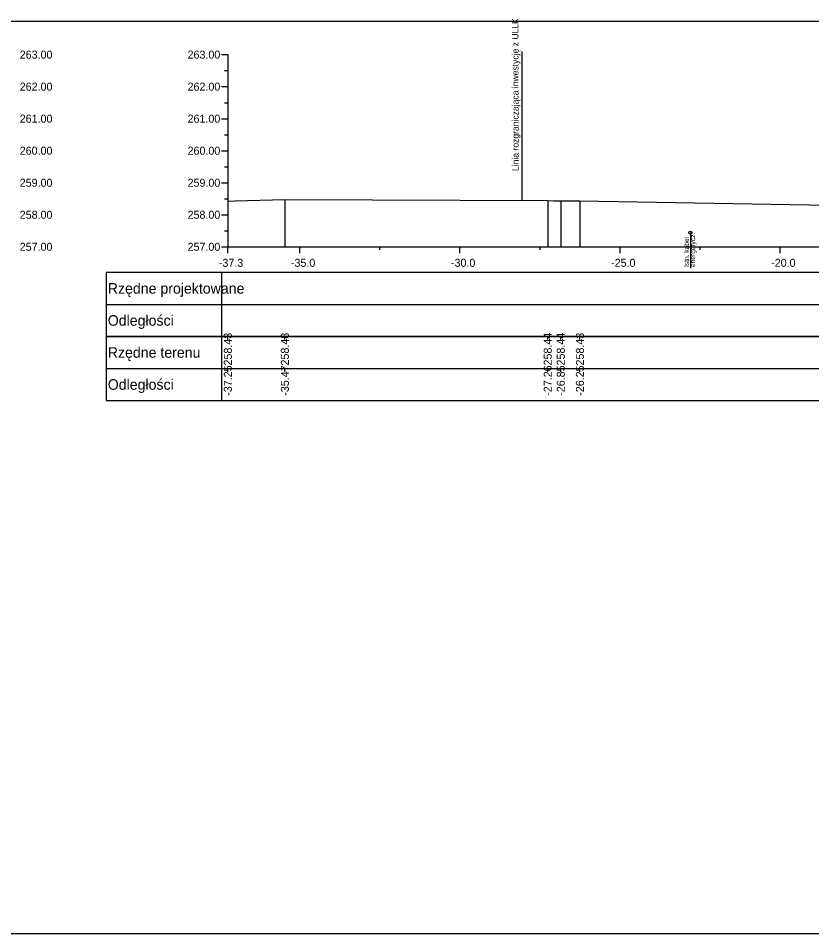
# Model space of a CAD drawing. Extents: x 6516023 to 6560129, y 5513077 to 5529206.
# Drawn here: x 6516993.92 to 6517018.7, y 5514451.16 to 5514479.74 of the extents above; entities that cross this region are included whole.
import ezdxf

# ---------------------------------------------------------------- set-up
doc = ezdxf.new("R2010")
doc.units = 0
for name, color, linetype in [('TOR_PRZEK_P-kable', 7, 'Continuous'), ('TOR_PRZEK_P-tabelka istniejace', 7, 'Continuous'), ('TOR_PRZEK_P-tabelka projektowane', 7, 'Continuous'), ('TOR_PRZEK_P-teren istniejacy', 7, 'Continuous'), ('TOR_PRZEK_P-uklad odniesienia', 7, 'Continuous'), ('TOR_PS_T-granica PKP-projektowana', 7, 'Continuous'), ('TOR_RAMKI-ramka+tabelka 1', 7, 'Continuous')]:
    doc.layers.add(name, color=color, linetype=linetype)

msp = doc.modelspace()

# ---------------------------------------------------------------- linework, layer by layer
at = {"layer": 'TOR_PRZEK_P-kable'}
msp.add_line((6517014.909, 5514473.047), (6517014.909, 5514471.937), dxfattribs=at)
msp.add_circle((6517014.909, 5514473.047), 0.05, dxfattribs=at)
at = {"layer": 'TOR_PRZEK_P-tabelka istniejace'}
for p, q in [((6516996.663, 5514469.806), (6516996.663, 5514467.806)), ((6517000.263, 5514469.806), (6517000.263, 5514467.806)), ((6517000.463, 5514469.706), (6517000.463, 5514469.806)), ((6517002.244, 5514469.706), (6517002.244, 5514469.806)), ((6517010.454, 5514469.706), (6517010.454, 5514469.806)), ((6517010.861, 5514469.706), (6517010.861, 5514469.806)), ((6517011.459, 5514469.706), (6517011.459, 5514469.806)), ((6516996.663, 5514468.806), (6517080.463, 5514468.806)), ((6517000.463, 5514468.706), (6517000.463, 5514468.806)), ((6517002.244, 5514468.706), (6517002.244, 5514468.806)), ((6517010.454, 5514468.706), (6517010.454, 5514468.806)), ((6517010.861, 5514468.706), (6517010.861, 5514468.806)), ((6517011.459, 5514468.706), (6517011.459, 5514468.806))]:
    msp.add_line(p, q, dxfattribs=at)
for points in [[(6517000.463, 5514474.035), (6517000.463, 5514472.806), (6517000.463, 5514472.676), (6517000.463, 5514472.606)], [(6517002.244, 5514474.084), (6517002.244, 5514472.806), (6517002.244, 5514472.676), (6517002.244, 5514472.606)], [(6517010.454, 5514474.047), (6517010.454, 5514472.806), (6517010.454, 5514472.676), (6517010.454, 5514472.606)], [(6517010.861, 5514474.045), (6517010.861, 5514472.806), (6517010.861, 5514472.676), (6517010.861, 5514472.606)], [(6517011.459, 5514474.038), (6517011.459, 5514472.806), (6517011.459, 5514472.676), (6517011.459, 5514472.606)]]:
    msp.add_lwpolyline(points, dxfattribs=at)
msp.add_lwpolyline([(6516996.663, 5514469.806), (6516996.663, 5514467.806), (6517080.463, 5514467.806), (6517080.463, 5514469.806)], close=True, dxfattribs=at)
at = {"layer": 'TOR_PRZEK_P-tabelka projektowane'}
for p, q in [((6516996.663, 5514471.806), (6516996.663, 5514469.806)), ((6517000.263, 5514471.806), (6517000.263, 5514469.806)), ((6516996.663, 5514470.806), (6517080.463, 5514470.806))]:
    msp.add_line(p, q, dxfattribs=at)
msp.add_lwpolyline([(6516996.663, 5514471.806), (6516996.663, 5514469.806), (6517080.463, 5514469.806), (6517080.463, 5514471.806)], close=True, dxfattribs=at)
at = {"layer": 'TOR_PRZEK_P-teren istniejacy'}
msp.add_lwpolyline([(6517000.463, 5514474.035), (6517000.688, 5514474.045), (6517002.244, 5514474.084), (6517010.454, 5514474.047), (6517010.631, 5514474.043), (6517010.861, 5514474.045), (6517010.922, 5514474.044), (6517011.459, 5514474.038), (6517020.423, 5514473.889)], dxfattribs=at)
at = {"layer": 'TOR_PRZEK_P-uklad odniesienia'}
for p, q in [((6517000.263, 5514478.606), (6517000.463, 5514478.606)), ((6517000.463, 5514478.606), (6517000.463, 5514472.606)), ((6517000.363, 5514478.106), (6517000.463, 5514478.106)), ((6517000.263, 5514477.606), (6517000.463, 5514477.606)), ((6517000.363, 5514477.106), (6517000.463, 5514477.106)), ((6517000.263, 5514476.606), (6517000.463, 5514476.606)), ((6517000.363, 5514476.106), (6517000.463, 5514476.106)), ((6517000.263, 5514475.606), (6517000.463, 5514475.606)), ((6517000.363, 5514475.106), (6517000.463, 5514475.106)), ((6517000.263, 5514474.606), (6517000.463, 5514474.606)), ((6517000.363, 5514474.106), (6517000.463, 5514474.106)), ((6517000.263, 5514473.606), (6517000.463, 5514473.606)), ((6517000.363, 5514473.106), (6517000.463, 5514473.106)), ((6517000.263, 5514472.606), (6517000.463, 5514472.606)), ((6517000.463, 5514472.606), (6517080.463, 5514472.606)), ((6517000.463, 5514472.506), (6517000.463, 5514472.606)), ((6517000.463, 5514472.406), (6517000.463, 5514472.606)), ((6517002.713, 5514472.406), (6517002.713, 5514472.606)), ((6517005.213, 5514472.506), (6517005.213, 5514472.606)), ((6517007.713, 5514472.406), (6517007.713, 5514472.606)), ((6517010.213, 5514472.506), (6517010.213, 5514472.606)), ((6517012.713, 5514472.406), (6517012.713, 5514472.606)), ((6517015.213, 5514472.506), (6517015.213, 5514472.606)), ((6517017.713, 5514472.406), (6517017.713, 5514472.606))]:
    msp.add_line(p, q, dxfattribs=at)
at = {"layer": 'TOR_PS_T-granica PKP-projektowana'}
msp.add_line((6517009.653, 5514474.05), (6517009.653, 5514478.708), dxfattribs=at)
at = {"layer": 'TOR_RAMKI-ramka+tabelka 1'}
msp.add_lwpolyline([(6516907.013, 5514479.656), (6517154.513, 5514479.656), (6517154.513, 5514451.156), (6516907.013, 5514451.156)], close=True, dxfattribs=at)

# ---------------------------------------------------------------- texts
at = {"layer": 'TOR_PRZEK_P-kable'}
for s, p in [('Istn. kabel', (6517014.864, 5514471.974)), ('energetycz.', (6517015.058, 5514471.974))]:
    msp.add_text(s, height=0.14999, rotation=90.0511, dxfattribs=at).set_placement(p)
at = {"layer": 'TOR_PRZEK_P-tabelka istniejace'}
for s, p in [('258.43', (6517000.588, 5514468.898)), ('258.48', (6517002.369, 5514468.898)), ('258.44', (6517010.579, 5514468.899)), ('258.44', (6517010.986, 5514468.899)), ('258.43', (6517011.584, 5514468.898)), ('-37.25', (6517000.588, 5514467.953)), ('-35.47', (6517002.369, 5514467.955)), ('-27.26', (6517010.579, 5514467.954)), ('-26.85', (6517010.986, 5514467.953)), ('-26.25', (6517011.584, 5514467.953))]:
    msp.add_text(s, height=0.25, rotation=90, dxfattribs=at).set_placement(p)
for s, p in [('Rzędne terenu', (6516996.713, 5514469.141)), ('Odległości', (6516996.713, 5514468.141))]:
    msp.add_text(s, height=0.33, dxfattribs=at).set_placement(p)
at = {"layer": 'TOR_PRZEK_P-tabelka projektowane'}
for s, p in [('Rzędne projektowane', (6516996.713, 5514471.141)), ('Odległości', (6516996.713, 5514470.141))]:
    msp.add_text(s, height=0.33, dxfattribs=at).set_placement(p)
at = {"layer": 'TOR_PRZEK_P-uklad odniesienia'}
for s, height, p in [('263.00', 0.25, (6516993.963, 5514478.481)), ('263.00', 0.25, (6516999.205, 5514478.481)), ('262.00', 0.25, (6516993.963, 5514477.481)), ('262.00', 0.25, (6516999.205, 5514477.481)), ('261.00', 0.25, (6516993.963, 5514476.481)), ('261.00', 0.25, (6516999.205, 5514476.481)), ('260.00', 0.25, (6516993.963, 5514475.481)), ('260.00', 0.25, (6516999.205, 5514475.481)), ('259.00', 0.25, (6516993.963, 5514474.481)), ('259.00', 0.25, (6516999.205, 5514474.481)), ('258.00', 0.25, (6516993.963, 5514473.481)), ('258.00', 0.25, (6516999.205, 5514473.481)), ('257.00', 0.25, (6516993.963, 5514472.481)), ('257.00', 0.25, (6516999.205, 5514472.481)), ('-', 0.0001, (6517000.463, 5514472.606)), ('-37.3', 0.25, (6517000.182, 5514471.981)), ('-35.0', 0.25, (6517002.432, 5514471.981)), ('-30.0', 0.25, (6517007.432, 5514471.981)), ('-25.0', 0.25, (6517012.432, 5514471.981)), ('-20.0', 0.25, (6517017.432, 5514471.981))]:
    msp.add_text(s, height=height, dxfattribs=at).set_placement(p)
at = {"layer": 'TOR_PS_T-granica PKP-projektowana'}
msp.add_text('Linia rozgraniczająca inwestycję z ULLK', height=0.2, rotation=90.0511, dxfattribs=at).set_placement((6517009.543, 5514474.972))

doc.saveas('drawing.dxf')
